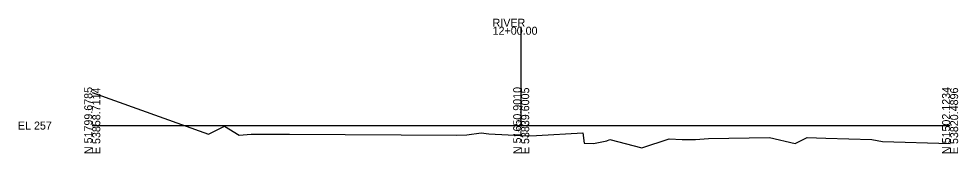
# Model space of a CAD drawing. Extents: x 5628 to 5956, y 92469 to 104012.
# Drawn here: x 5627.6 to 5956.2, y 101468.9 to 101516 of the extents above; entities that cross this region are included whole.
import ezdxf

# ---------------------------------------------------------------- set-up
doc = ezdxf.new("R2010")
doc.units = 0
for name, color, linetype in [('Level 10', 7, 'Continuous'), ('Level 60', 7, 'Continuous'), ('Level 63', 7, 'Continuous')]:
    doc.layers.add(name, color=color, linetype=linetype)

msp = doc.modelspace()

# ---------------------------------------------------------------- linework, layer by layer
at = {"layer": 'Level 60'}
for p, q in [((5653.34, 101490.14), (5694.03, 101475.55)), ((5694.03, 101475.55), (5699.64, 101478.35)), ((5699.64, 101478.35), (5704.75, 101475.29)), ((5704.75, 101475.29), (5708.9, 101475.58)), ((5708.9, 101475.58), (5722.33, 101475.55)), ((5722.33, 101475.55), (5780.88, 101475.29)), ((5780.88, 101475.29), (5784.35, 101475.4)), ((5784.35, 101475.4), (5789.32, 101476.04)), ((5789.32, 101476.04), (5792.01, 101475.75)), ((5792.01, 101475.75), (5803.34, 101475.14)), ((5803.34, 101475.14), (5805.27, 101475.04)), ((5805.27, 101475.04), (5808.7, 101475.16)), ((5808.7, 101475.16), (5824.9, 101476)), ((5824.9, 101476), (5825.39, 101472.41)), ((5868.84, 101474.05), (5890.14, 101474.47)), ((5890.14, 101474.47), (5899.15, 101472.37)), ((5899.15, 101472.37), (5903.39, 101474.41)), ((5903.39, 101474.41), (5909.9, 101474.13)), ((5825.39, 101472.41), (5828.68, 101472.3)), ((5828.68, 101472.3), (5833.26, 101473.24)), ((5833.26, 101473.24), (5834.36, 101473.66)), ((5834.36, 101473.66), (5845.51, 101470.8)), ((5845.51, 101470.8), (5855.1, 101473.93)), ((5855.1, 101473.93), (5859.62, 101473.73)), ((5859.62, 101473.73), (5864.32, 101473.73)), ((5864.32, 101473.73), (5868.84, 101474.05)), ((5909.9, 101474.13), (5926.02, 101473.67)), ((5926.02, 101473.67), (5929.66, 101473.03)), ((5929.66, 101473.03), (5953.34, 101472.32))]:
    msp.add_line(p, q, dxfattribs=at)
at = {"layer": 'Level 63'}
for p, q in [((5803.34, 101478.6), (5803.34, 101513.22)), ((5653.34, 101478.6), (5803.34, 101478.6)), ((5803.34, 101478.6), (5953.34, 101478.6))]:
    msp.add_line(p, q, dxfattribs=at)

# ---------------------------------------------------------------- texts
at = {"layer": 'Level 10'}
msp.add_text('255.27', height=1.2, rotation=90, dxfattribs=at).set_placement((5803.54, 101476.14))
at = {"layer": 'Level 63'}
for s, p in [('RIVER', (5793.34, 101513.22)), ('12+00.00', (5793.34, 101510.42)), ('EL 257', (5627.33, 101477.2))]:
    msp.add_text(s, height=2.8, dxfattribs=at).set_placement(p)
for s, p in [('N 51799.6785', (5653.34, 101468.6)), ('E 53858.7114', (5656.14, 101468.6)), ('N 51650.9010', (5803.34, 101468.6)), ('E 53839.6005', (5806.14, 101468.6)), ('N 51502.1234', (5953.34, 101468.6)), ('E 53820.4896', (5956.14, 101468.59))]:
    msp.add_text(s, height=2.8, rotation=90, dxfattribs=at).set_placement(p)

doc.saveas('drawing.dxf')
